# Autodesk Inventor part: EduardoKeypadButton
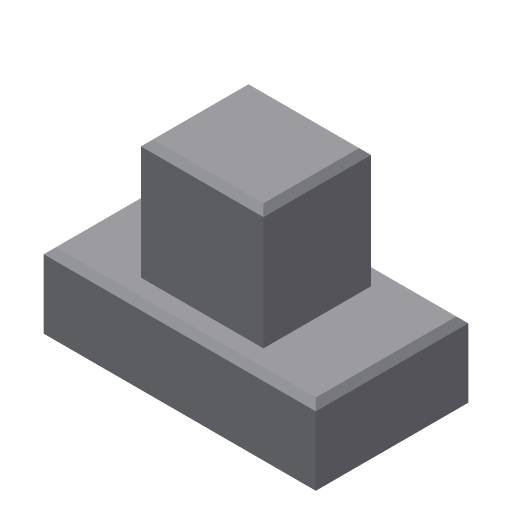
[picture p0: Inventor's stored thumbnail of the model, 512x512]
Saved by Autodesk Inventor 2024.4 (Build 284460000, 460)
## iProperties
Created: 2025-03
Part Number: EduardoKeypadButton
Material: Standard
Document SubType Name: Modeling
Designer: offt
Density: 1 g/cm^3
Appearance: Vorgabe
Author: offt
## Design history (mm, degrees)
sketch "Skizze1"
  geometry: L1 (-28.235, 9.323)-(-19.135, 9.323); L2 (-19.135, 9.323)-(-19.135, 4.223); L3 (-19.135, 4.223)-(-28.235, 4.223); L4 (-28.235, 4.223)-(-28.235, 9.323)
  constraints: 8 end point, 2 parallel, 1 horizontal, 1 perpendicular
  dimensions: "d0" = 9.1 distance of L1.start L1.end; "d1" = 5.1 distance of L3.end L1.start
extrude "Extrusion1" new body sketch "Skizze1" distance "d2" = 2.5; taper "d3" = 0 deg
sketch "Skizze2"
  geometry: L1 (-28.235, 4.223)-(-28.235, 9.323) reference; L2 (-28.235, 9.323)-(-19.135, 9.323) reference; L3 (-19.135, 9.323)-(-19.135, 4.223) reference; L4 (-19.135, 4.223)-(-28.235, 4.223) reference; L5 (-25.735, 8.573)-(-21.635, 8.573); L6 (-21.635, 8.573)-(-21.635, 4.973); L7 (-21.635, 4.973)-(-25.735, 4.973); L8 (-25.735, 4.973)-(-25.735, 8.573); 2 further points
  constraints: 8 end point, 2 parallel, 1 horizontal, 1 midpoint, 1 perpendicular
  dimensions: "d4" = 4.1 distance of L5.start L5.end; "d5" = 3.6 distance of L5.end L6.end; "d6" = 9.1 distance of L1.end L2.end (derived); "d7" = 5.1 distance of L1.start L1.end (derived); "d8" = 0.75 distance between parallel lines of L2 L5 (= -0.5 x d5 + 0.5 x d7); "d9" = 2.5 distance from line of point (-28.235, 6.773) L8 (= -0.5 x d4 + 0.5 x d6)
extrude "Extrusion2" join sketch "Skizze2" distance "d10" = 4; taper "d11" = 0 deg
sketch "Skizze3"
  geometry: L1 (28.235, 9.323)-(28.235, 4.223) reference; L2 (28.235, 4.223)-(19.135, 4.223) reference; L3 (19.135, 4.223)-(19.135, 9.323) reference; L4 (19.135, 9.323)-(28.235, 9.323) reference; L5 (24.685, 5.773)-(22.685, 5.773); L6 (22.685, 5.773)-(22.685, 7.773); L7 (22.685, 7.773)-(24.685, 7.773); L8 (24.685, 7.773)-(24.685, 5.773); 2 further points
  constraints: 8 end point, 2 parallel, 1 horizontal, 1 midpoint, 1 perpendicular
  dimensions: "d12" = 9.1 distance of L1.end L2.end (derived); "d13" = 5.1 distance of L1.start L1.end (derived); "d14" = 2 distance of L5.start L5.end; "d15" = 2 distance of L7.end L5.start; "d16" = 3.55 distance between parallel lines of L3 L6 (= -0.5 x d14 + 0.5 x d12); "d17" = 1.55 distance from line of point (23.685, 4.223) L5 (= -0.5 x d15 + 0.5 x d13)
extrude "Extrusion3" cut sketch "Skizze3" distance "d18" = 4; taper "d19" = 0 deg
chamfer "Fasen1" distance "d20" = 0.2; stored, may be unused: second distance "d21" = 2, angle "d22" = 45 deg
node "Volumenkörper1"
node "Volumenkörper"
node "Flächenkörper"
node "Schnittkanten projizieren1"
node "Schnittkanten projizieren2"
